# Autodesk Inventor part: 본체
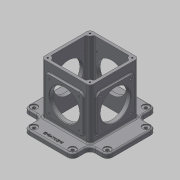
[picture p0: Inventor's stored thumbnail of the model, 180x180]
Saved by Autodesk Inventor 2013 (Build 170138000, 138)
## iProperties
Created: 2018-09
Part Number: 본체
Material: 일반
Document SubType Name: Modeling
Designer: mduedu
Density: 1 g/cm^3
Author: mduedu
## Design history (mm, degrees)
sketch "스케치1"
  geometry: L1 (90, 52.5)-(-90, 52.5); L2 (-90, 52.5)-(-90, -52.5); L3 (-90, -52.5)-(90, -52.5); L4 (90, -52.5)-(90, 52.5); L5 (90, 52.5)-(-90, -52.5); L6 (-90, 52.5)-(90, -52.5); L7 (-52.5, -90)-(52.5, -90); L8 (52.5, -90)-(52.5, 90); L9 (52.5, 90)-(-52.5, 90); L10 (-52.5, 90)-(-52.5, -90); L11 (-52.5, -90)-(52.5, 90); L12 (52.5, -90)-(-52.5, 90); 1 further point
  constraints: 24 end point, 4 midpoint, 4 parallel, 2 horizontal, 2 perpendicular
  dimensions: "d0" = 180 distance of L3.end L2.end; "d1" = 105 distance of L2.end L1.end; "d105" = 105 distance of L9.end L8.end; "d106" = 180 distance of L8.end L7.end
extrude "돌출1" new body sketch "스케치1" distance "d2" = 10; taper "d3" = 0 deg
fillet "모깎기16" dims "d107" = 11
sketch "스케치2"
  geometry: L1 (-52.5, -52.5)-(52.5, -52.5); L2 (52.5, -52.5)-(52.5, 52.5); L3 (52.5, 52.5)-(-52.5, 52.5); L4 (-52.5, 52.5)-(-52.5, -52.5); L5 (-52.5, -52.5)-(52.5, 52.5); L6 (52.5, -52.5)-(-52.5, 52.5); 1 further point
  constraints: 12 end point, 2 midpoint, 2 parallel, 1 horizontal, 1 perpendicular
  dimensions: "d4" = 105 distance of L3.end L2.end; "d5" = 105 distance of L2.end L1.end
extrude "돌출2" join sketch "스케치2" distance "d6" = 110; taper "d7" = 0 deg
sketch "스케치14"
  geometry: L1 (-52.5, 52.5)-(52.5, 52.5) reference; L2 (52.5, 52.5)-(52.5, -52.5) reference; L3 (52.5, -52.5)-(-52.5, -52.5) reference; L4 (-52.5, -52.5)-(-52.5, 52.5) reference; L5 (46.5, 46.5)-(-46.5, 46.5); L6 (-46.5, 46.5)-(-46.5, -46.5); L7 (-46.5, -46.5)-(46.5, -46.5); L8 (46.5, -46.5)-(46.5, 46.5); 1 further point
  constraints: 8 end point, 3 other
  dimensions: "d85" = 6 distance between parallel lines of L5 L1
extrude "돌출10" cut sketch "스케치14" stored distance "d86" = 10; taper "d87" = 0 deg
fillet "모깎기1" dims "d12" = 7
sketch "스케치15"
  geometry: A1 r 7 centre (-45.5, 45.5) between (-45.5, 52.5) and (-52.5, 45.5) reference; A2 r 7 centre (45.5, 45.5) between (52.5, 45.5) and (45.5, 52.5) reference; A3 r 7 centre (45.5, -45.5) between (45.5, -52.5) and (52.5, -45.5) reference; A4 r 7 centre (-45.5, -45.5) between (-52.5, -45.5) and (-45.5, -52.5) reference; 5 further points
  constraints: 4 coincident, 4 vertical alignment, 8 other
extrude "돌출11" join sketch "스케치15" stored distance "d88" = 10; taper "d89" = 0 deg
fillet "모깎기15" dims "d90" = 3
sketch "스케치6"
  geometry: L1 (50, 20)-(130, 20); L2 (130, 20)-(130, 100); L3 (130, 100)-(50, 100); L4 (50, 100)-(50, 20); L5 (50, 20)-(130, 100); L6 (130, 20)-(50, 100); L7 (0, 0)-(180, 0) reference; 4 further points
  constraints: 12 end point, 4 midpoint, 2 parallel, 1 horizontal, 1 perpendicular, 1 vertical alignment
  dimensions: "d25" = 80 distance of L3.end L2.end; "d26" = 80 distance of L2.end L1.end; "d27" = 60 distance of point (90, 0) point (90, 60)
extrude "돌출6" join sketch "스케치6" distance "d28" = 3; taper "d29" = 0 deg
fillet "모깎기7" dims "d30" = 8
sketch "스케치7"
  geometry: C1 r 32.5 at (90, 60); 1 further point
  constraints: 1 centre point, 1 vertical alignment
  dimensions: "d32" = 65 diameter of C1; "d33" = 60 distance of C1.centre point (90, 0)
extrude "돌출7" cut sketch "스케치7" stored distance "d34" = 3; taper "d35" = 0 deg
fillet "모깎기9" dims "d36" = 3
sketch "스케치8"
  geometry: L1 (5.5, 10)-(85.5, 10); L2 (85.5, 10)-(85.5, 90); L3 (85.5, 90)-(5.5, 90); L4 (5.5, 90)-(5.5, 10); L5 (5.5, 10)-(85.5, 90); L6 (85.5, 10)-(5.5, 90); L7 (-7, -10)-(98, -10) reference; C1 r 32.5 at (45.5, 50); 4 further points
  constraints: 12 end point, 4 midpoint, 2 parallel, 1 centre point, 1 coincident, 1 horizontal, 1 perpendicular, 1 vertical alignment
  dimensions: "d37" = 80 distance of L3.end L2.end; "d38" = 80 distance of L2.end L1.end; "d39" = 60 distance from line of point (45.5, 50) L7; "d40" = 65 diameter of C1
extrude "돌출8" join sketch "스케치8" distance "d41" = 3; taper "d42" = 0 deg
fillet "모깎기10" dims "d43" = 8
extrude "돌출9" cut sketch "스케치8" stored distance "d44" = 3; taper "d45" = 0 deg
fillet "모깎기11" dims "d46" = 3
sketch "스케치9"
  geometry: L1 (50, 92)-(50, 28) reference; L2 (58, 20)-(122, 20) reference; L3 (130, 28)-(130, 92) reference; L4 (122, 100)-(58, 100) reference; C1 r 32.5 at (90, 60) reference; A1 r 8 centre (58, 92) between (58, 100) and (50, 92) reference; A2 r 8 centre (58, 28) between (50, 28) and (58, 20) reference; A3 r 8 centre (122, 28) between (122, 20) and (130, 28) reference; A4 r 8 centre (122, 92) between (130, 92) and (122, 100) reference; 5 further points
  constraints: 4 coincident
hole "구멍1" sketch "스케치9" at (58, 92), (122, 92), (122, 28), (58, 28) diameter "d47" = 3.242; stored, may be unused: countersink angle "d51" = 90 deg, drill point angle "d53" = 118 deg; dims "d48" = 6, "d49" = 4, "d50" = 2, "d52" = 9
sketch "스케치10"
  geometry: L1 (13.5, 10)-(77.5, 10) reference; L2 (85.5, 18)-(85.5, 82) reference; L3 (77.5, 90)-(13.5, 90) reference; L4 (5.5, 82)-(5.5, 18) reference; C1 r 32.5 at (45.5, 50) reference; A1 r 8 centre (13.5, 18) between (5.5, 18) and (13.5, 10) reference; A2 r 8 centre (77.5, 18) between (77.5, 10) and (85.5, 18) reference; A3 r 8 centre (77.5, 82) between (85.5, 82) and (77.5, 90) reference; A4 r 8 centre (13.5, 82) between (13.5, 90) and (5.5, 82) reference; 5 further points
  constraints: 4 coincident
hole "구멍2" sketch "스케치10" at (13.5, 82), (77.5, 82), (77.5, 18), (13.5, 18) diameter "d54" = 3.242; stored, may be unused: countersink angle "d58" = 90 deg, drill point angle "d60" = 118 deg; dims "d55" = 6, "d56" = 4, "d57" = 2, "d59" = 9
fillet "모깎기12" dims "d68" = 11
sketch "스케치16"
  geometry: A1 r 11 centre (-79, 41.5) between (-79, 52.5) and (-90, 41.5) reference; A2 r 11 centre (-79, -41.5) between (-90, -41.5) and (-79, -52.5) reference; A3 r 11 centre (79, 41.5) between (90, 41.5) and (79, 52.5) reference; A4 r 11 centre (79, -41.5) between (79, -52.5) and (90, -41.5) reference; A5 r 11 centre (-41.5, 79) between (-41.5, 90) and (-52.5, 79) reference; A6 r 11 centre (41.5, 79) between (52.5, 79) and (41.5, 90) reference; A7 r 11 centre (41.5, -79) between (41.5, -90) and (52.5, -79) reference; A8 r 11 centre (-41.5, -79) between (-52.5, -79) and (-41.5, -90) reference; 9 further points
  constraints: 8 coincident
hole "구멍5" sketch "스케치16" at (-79, 41.5), (79, 41.5), (79, -41.5), (-79, -41.5), (41.5, 79), (-41.5, 79), (-41.5, -79), (41.5, -79) diameter "d91" = 6.6; stored, may be unused: countersink angle "d95" = 90 deg, drill point angle "d97" = 118 deg; dims "d92" = 6, "d93" = 15, "d94" = 2, "d96" = 8
fillet "모깎기13" dims "d77" = 3
chamfer "모따기1" distance "d79" = 1; stored, may be unused: second distance "d80" = 2, angle "d81" = 45 deg
sketch "스케치17"
  geometry: A1 r 7 centre (-45.5, 45.5) between (-45.5, 52.5) and (-52.5, 45.5) reference; A2 r 7 centre (-45.5, -45.5) between (-52.5, -45.5) and (-45.5, -52.5) reference; A3 r 7 centre (45.5, -45.5) between (45.5, -52.5) and (52.5, -45.5) reference; A4 r 7 centre (45.5, 45.5) between (52.5, 45.5) and (45.5, 52.5) reference; 5 further points
  constraints: 4 coincident
hole "구멍6" sketch "스케치17" at (-45.5, 45.5), (45.5, 45.5), (45.5, -45.5), (-45.5, -45.5) diameter "d98" = 3.242; stored, may be unused: countersink angle "d102" = 90 deg, drill point angle "d104" = 118 deg; dims "d99" = 8, "d100" = 15, "d101" = 2, "d103" = 10
sketch "스케치13"
  geometry: L1 (90, -41.5)-(90, 41.5) reference; 2 further points
  constraints: 1 horizontal alignment, 1 other
  dimensions: "d82" = 11 distance from line of point (79, 0) L1
feature "엠보싱1" sketch "스케치13" dims "d0" = 180, "d1" = 105, "d83" = 0.5, "d84" = 0
node "솔리드1"
mirror "대칭1"
mirror "대칭4"
mirror "대칭2"
mirror "대칭5"
node "투영된 루프2"
node "투영된 루프3"
node "투영된 루프6"
